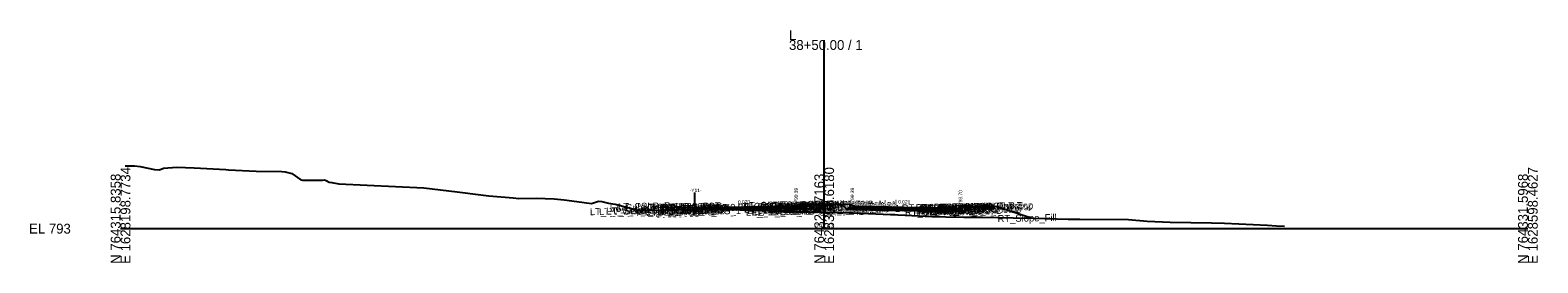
# Model space of a CAD drawing. Extents: x -26 to 4403, y -510 to 9556.
# Drawn here: x 1974.3 to 2402.8, y 8490.3 to 8556.3 of the extents above; entities that cross this region are included whole.
import ezdxf

# ---------------------------------------------------------------- set-up
doc = ezdxf.new("R2010")
doc.units = 0
for name, color, linetype in [('Default', 7, 'Continuous'), ('Exist CMT Pavement', 7, 'Continuous'), ('Exist Cross Section Cell', 7, 'Continuous'), ('Exist XS Center Line Elevation Label', 7, 'Continuous'), ('Exist XS Ground Line', 7, 'Continuous'), ('Prop CMT Conc Surface', 7, 'Continuous'), ('Prop CMT Concrete Structures', 7, 'Continuous'), ('Prop CMT Pvmt Course 1', 7, 'Continuous'), ('Prop CMT Pvmt Course 1 CG', 7, 'Continuous'), ('Prop CMT Pvmt Course 2', 7, 'Continuous'), ('Prop CMT Pvmt Course 2 Wedge', 7, 'Continuous'), ('Prop CMT Pvmt Course 3', 7, 'Continuous'), ('Prop CMT Pvmt Course 3 Wedge', 7, 'Continuous'), ('Prop CMT Pvmt Surface', 7, 'Continuous'), ('Prop CMT Shear Line', 7, 'Continuous'), ('Prop CMT Slope Grass', 7, 'Continuous'), ('Prop CMT Subgrade Earthwork', 7, 'Continuous'), ('Prop XS Hydro Elevations', 7, 'Continuous'), ('Prop XS SE Text', 7, 'Continuous'), ('Prop XS Side Slope Text', 7, 'Continuous'), ('Scratch_Level_0', 7, 'Continuous')]:
    doc.layers.add(name, color=color, linetype=linetype)

msp = doc.modelspace()

# ---------------------------------------------------------------- linework, layer by layer
at = {"layer": 'Exist CMT Pavement'}
msp.add_lwpolyline([(2163.25, 8505.47), (2164.49, 8505.46), (2172.09, 8505.45), (2179.81, 8505.29), (2182.05, 8505.24), (2184.11, 8505.16), (2191.16, 8504.91)], dxfattribs=at)
at = {"layer": 'Exist Cross Section Cell'}
for p, q in [((2200, 8500), (2200, 8553.53)), ((2000, 8500), (2200, 8500)), ((2200, 8500), (2400, 8500))]:
    msp.add_line(p, q, dxfattribs=at)
at = {"layer": 'Exist XS Ground Line'}
msp.add_lwpolyline([(2001.33, 8517.83), (2003.92, 8517.84), (2005.57, 8517.68), (2009.64, 8516.83), (2011.1, 8516.7), (2012.25, 8517.13), (2015.99, 8517.44), (2020.92, 8517.24), (2029.9, 8516.75), (2030.69, 8516.73), (2038.52, 8516.36), (2045.82, 8516.21), (2046.75, 8516.1), (2048.71, 8515.64), (2051.26, 8513.85), (2051.74, 8513.81), (2052.37, 8513.81), (2054.68, 8513.79), (2057.44, 8513.77), (2058.01, 8513.83), (2058.47, 8513.7), (2059.34, 8513.22), (2060.03, 8513.07), (2062, 8512.77), (2086.24, 8511.62), (2095.72, 8510.45), (2102.42, 8509.62), (2104.66, 8509.31), (2111.64, 8508.76), (2113.24, 8508.6), (2118.29, 8508.61), (2120.7, 8508.54), (2123.29, 8508.47), (2126.13, 8508.21), (2129.69, 8507.71), (2133.88, 8507.18), (2135.88, 8507.77), (2136.76, 8507.75), (2138.69, 8507.2), (2140.55, 8506.91), (2147.02, 8505.21), (2148.45, 8505.11), (2149.98, 8505.11), (2162.31, 8505.47), (2164.49, 8505.46), (2172.09, 8505.45), (2179.81, 8505.29), (2182.05, 8505.24), (2184.11, 8505.16), (2191.16, 8504.91), (2191.68, 8504.84), (2192.06, 8504.79), (2195.56, 8504.77), (2200, 8504.67), (2207.1, 8504.51), (2207.84, 8504.52), (2208.25, 8504.46), (2214.7, 8504.2), (2222.98, 8503.83), (2230.63, 8503.47), (2232.19, 8503.45), (2234.59, 8503.37), (2239.67, 8503.28), (2244.98, 8503.25), (2258.07, 8503.02), (2258.61, 8503.05), (2259.39, 8503), (2269.35, 8502.73), (2272.69, 8502.65), (2286.48, 8502.6), (2291.82, 8502.08), (2298.32, 8501.88), (2310.04, 8501.66), (2313.82, 8501.58), (2326.04, 8501.02), (2328.54, 8500.83), (2330.86, 8500.75)], dxfattribs=at)
at = {"layer": 'Prop CMT Conc Surface'}
for points in [[(2191.25, 8506.38), (2192, 8506.39), (2192, 8506.56), (2192.76, 8506.81)], [(2208.75, 8506.38), (2208, 8506.39), (2208, 8506.56), (2207.24, 8506.81)], [(2243.25, 8506.29), (2248.25, 8506.39)], [(2236.75, 8505.82), (2238.75, 8505.7)], [(2238.75, 8505.7), (2238.75, 8506.2), (2239.25, 8506.2)]]:
    msp.add_lwpolyline(points, dxfattribs=at)
at = {"layer": 'Prop CMT Concrete Structures'}
for points in [[(2191.25, 8506.38), (2192, 8506.39), (2192, 8506.56), (2192.76, 8506.81)], [(2191.25, 8505.79), (2191.25, 8506.38)], [(2192.76, 8506.81), (2192.76, 8505.82)], [(2208.75, 8506.38), (2208, 8506.39), (2208, 8506.56), (2207.24, 8506.81)], [(2207.24, 8506.81), (2207.24, 8505.82)], [(2208.75, 8505.79), (2208.75, 8506.38)], [(2248.25, 8506.39), (2243.25, 8506.29)], [(2248.25, 8506.05), (2248.25, 8506.39)], [(2163.25, 8505.23), (2163.25, 8505.82)], [(2192.76, 8505.82), (2191.25, 8505.79)], [(2207.24, 8505.82), (2208.75, 8505.79)], [(2236.75, 8505.82), (2238.75, 8505.7), (2238.75, 8506.2), (2239.25, 8506.2)], [(2239.25, 8506.2), (2239.25, 8505.18), (2236.75, 8505.23)], [(2236.75, 8505.23), (2236.75, 8505.82)], [(2243.25, 8506.29), (2243.25, 8505.95)], [(2243.25, 8505.95), (2248.25, 8506.05)]]:
    msp.add_lwpolyline(points, dxfattribs=at)
at = {"layer": 'Prop CMT Pvmt Course 1'}
for points in [[(2191.25, 8506.38), (2163.25, 8505.82)], [(2191.25, 8506.13), (2191.25, 8506.38)], [(2208.75, 8506.38), (2236.75, 8505.82)], [(2208.75, 8506.13), (2208.75, 8506.38)], [(2163.25, 8505.57), (2191.16, 8506.13), (2191.25, 8506.13)], [(2163.25, 8505.82), (2163.25, 8505.57), (2163.25, 8505.57)], [(2236.75, 8505.57), (2208.75, 8506.13)], [(2208.75, 8506.13), (2208.75, 8506.13), (2208.75, 8506.13)], [(2236.75, 8505.82), (2236.75, 8505.57)]]:
    msp.add_lwpolyline(points, dxfattribs=at)
at = {"layer": 'Prop CMT Pvmt Course 1 CG'}
for points in [[(2163.25, 8504.9), (2163.25, 8505.23)], [(2191.25, 8505.79), (2193.26, 8505.83), (2193.59, 8505.51)], [(2191.25, 8505.46), (2191.25, 8505.79)], [(2193.59, 8505.51), (2191.25, 8505.46)], [(2208.75, 8505.79), (2206.74, 8505.83), (2206.41, 8505.51)], [(2206.41, 8505.51), (2208.75, 8505.46)], [(2208.75, 8505.46), (2208.75, 8505.79)], [(2236.75, 8505.23), (2239.75, 8505.17), (2240.09, 8504.83)], [(2236.75, 8504.9), (2236.75, 8505.23)], [(2240.09, 8504.83), (2236.75, 8504.9)]]:
    msp.add_lwpolyline(points, dxfattribs=at)
at = {"layer": 'Prop CMT Pvmt Course 2'}
for points in [[(2163.25, 8505.23), (2163.25, 8505.23), (2163.25, 8505.57), (2163.25, 8505.57)], [(2163.25, 8505.57), (2163.25, 8505.23)], [(2191.16, 8506.13), (2191.16, 8505.79)], [(2191.25, 8506.13), (2191.16, 8506.13)], [(2191.16, 8505.79), (2191.25, 8505.79)], [(2191.25, 8505.79), (2191.25, 8506.13)], [(2208.75, 8505.79), (2208.75, 8506.13)], [(2208.75, 8506.13), (2236.75, 8505.57)], [(2236.75, 8505.23), (2208.75, 8505.79)], [(2236.75, 8505.57), (2236.75, 8505.23)]]:
    msp.add_lwpolyline(points, dxfattribs=at)
at = {"layer": 'Prop CMT Pvmt Course 2 Wedge'}
for points in [[(2163.25, 8505.57), (2164.49, 8505.59), (2172.09, 8505.74), (2179.81, 8505.9), (2182.05, 8505.94), (2184.11, 8505.98), (2191.16, 8506.13), (2191.16, 8506.13)], [(2191.16, 8505.79), (2191.16, 8505.79), (2184.11, 8505.65), (2182.05, 8505.61), (2179.81, 8505.57), (2173.06, 8505.43), (2172.09, 8505.45), (2164.49, 8505.46), (2163.25, 8505.47)], [(2163.25, 8505.47), (2163.25, 8505.57)], [(2191.16, 8506.13), (2191.16, 8505.79)]]:
    msp.add_lwpolyline(points, dxfattribs=at)
at = {"layer": 'Prop CMT Pvmt Course 3'}
for points in [[(2163.25, 8505.23), (2163.25, 8505.23), (2163.25, 8504.9), (2163.25, 8504.9)], [(2163.25, 8504.9), (2163.25, 8505.23)], [(2191.25, 8505.79), (2191.16, 8505.79)], [(2191.16, 8505.79), (2191.16, 8505.46)], [(2191.16, 8505.46), (2191.25, 8505.46)], [(2191.25, 8505.46), (2191.25, 8505.79)], [(2208.75, 8505.79), (2236.75, 8505.23)], [(2208.75, 8505.46), (2208.75, 8505.79)], [(2236.75, 8504.9), (2208.75, 8505.46)], [(2236.75, 8505.23), (2236.75, 8504.9)]]:
    msp.add_lwpolyline(points, dxfattribs=at)
at = {"layer": 'Prop CMT Pvmt Course 3 Wedge'}
for points in [[(2173.07, 8505.43), (2179.81, 8505.57)], [(2191.16, 8504.91), (2191.16, 8504.91), (2184.11, 8505.16), (2182.05, 8505.24), (2179.81, 8505.29), (2173.07, 8505.43)], [(2179.81, 8505.57), (2182.05, 8505.61), (2184.11, 8505.65), (2191.16, 8505.79), (2191.16, 8505.79)], [(2191.16, 8505.79), (2191.16, 8504.91)]]:
    msp.add_lwpolyline(points, dxfattribs=at)
at = {"layer": 'Prop CMT Pvmt Surface'}
for points in [[(2191.25, 8506.38), (2163.25, 8505.82)], [(2208.75, 8506.38), (2236.75, 8505.82)]]:
    msp.add_lwpolyline(points, dxfattribs=at)
at = {"layer": 'Prop CMT Shear Line'}
msp.add_line((2163.25, 8504.01), (2163.25, 8510.28), dxfattribs=at)
at = {"layer": 'Prop CMT Slope Grass'}
for points in [[(2192.76, 8506.81), (2200, 8506.95)], [(2207.24, 8506.81), (2200, 8506.95)], [(2239.25, 8506.2), (2248.75, 8506.39), (2258.81, 8503.03)]]:
    msp.add_lwpolyline(points, dxfattribs=at)
at = {"layer": 'Prop CMT Subgrade Earthwork'}
for points in [[(2194.93, 8506.85), (2193.59, 8505.51)], [(2205.07, 8506.85), (2206.41, 8505.51)], [(2163.25, 8504.9), (2163.25, 8505.23)], [(2163.25, 8504.9), (2163.25, 8504.9)], [(2163.25, 8504.9), (2163.25, 8504.9)], [(2191.25, 8505.46), (2191.16, 8505.46)], [(2191.16, 8505.46), (2191.16, 8504.91)], [(2193.59, 8505.51), (2191.25, 8505.46)], [(2191.25, 8505.46), (2191.25, 8505.46)], [(2206.41, 8505.51), (2208.75, 8505.46)], [(2208.75, 8505.46), (2236.75, 8504.9)], [(2208.75, 8505.46), (2208.75, 8505.46)], [(2208.75, 8505.46), (2208.75, 8505.46)], [(2236.75, 8504.9), (2240.09, 8504.83), (2241.5, 8506.24)], [(2236.75, 8504.9), (2236.75, 8504.9)]]:
    msp.add_lwpolyline(points, dxfattribs=at)

# ---------------------------------------------------------------- texts
at = {"layer": 'Default'}
msp.add_text('-', height=0.0001, dxfattribs=at).set_placement((2000, 8500))
at = {"layer": 'Exist Cross Section Cell'}
for s, p in [('38+50.00 / 1', (2190, 8550.73)), ('L', (2190, 8553.53)), ('EL 793', (1974, 8498.6))]:
    msp.add_text(s, height=2.8, dxfattribs=at).set_placement(p)
for s, p in [('N 764315.8358', (2000, 8490)), ('E 1628198.7734', (2002.8, 8490)), ('N 764323.7163', (2200, 8490)), ('E 1628398.6180', (2202.8, 8490)), ('N 764331.5968', (2400, 8490)), ('E 1628598.4627', (2402.8, 8490))]:
    msp.add_text(s, height=2.8, rotation=90, dxfattribs=at).set_placement(p)
at = {"layer": 'Exist XS Center Line Elevation Label'}
msp.add_text('797.67', height=1.2, dxfattribs=at).set_placement((2197.59, 8500.07))
at = {"layer": 'Prop XS Hydro Elevations'}
for s, rotation, p in [('-Y11-', 360, (2161.77, 8510.37)), ('799.39', 90, (2192.5, 8507.39)), ('799.39', 90, (2208.5, 8507.39)), ('798.70', 90, (2239.25, 8506.7))]:
    msp.add_text(s, height=1, rotation=rotation, dxfattribs=at).set_placement(p)
at = {"layer": 'Prop XS SE Text'}
for rotation, p in [(1.1458, (2175.48, 8507.06)), (358.8543, (2221.02, 8507.13))]:
    msp.add_text('0.020', height=1, rotation=rotation, dxfattribs=at).set_placement(p)
at = {"layer": 'Prop XS Side Slope Text'}
msp.add_text('3:1', height=1, rotation=341.5647, dxfattribs=at).set_placement((2253.26, 8505.67))
at = {"layer": 'Scratch_Level_0'}
for s, p in [('LT_Slope_Fill', (2138.13, 8503.98)), ('LT_Sub_Trench_Out_DLT', (2139.09, 8504.85)), ('LT_CSLP_Pnt', (2141.44, 8505.19)), ('LT_CG_Top_Face', (2148.53, 8504.94)), ('LT_CG_Top_BOC', (2149.06, 8504.96)), ('LT_CG_Bot_BOC', (2149.09, 8503.95)), ('LT_CG_Top_Gut', (2149.51, 8504.46)), ('38+50.00', (2152.66, 8505.09)), ('LT_PV2_OEEOP', (2152.58, 8504.35)), ('LT_PV3_OEEOP', (2152.58, 8504.02)), ('LT_CG_Bot_IE', (2153.19, 8504.03)), ('LT_PV2_OEOT', (2153.45, 8504.37)), ('LT_PV3_OEOT', (2153.45, 8504.04)), ('LT_PV1_OEOT', (2154.01, 8504.63)), ('38+50.00', (2154.21, 8505.06)), ('38+50.00', (2167.28, 8504.9)), ('LT_CG_Top_Face_Med', (2175.39, 8505.23)), ('LT_CG_Top_Gut_Med', (2176.37, 8505.08)), ('LT_CG_Top_BOC_Med', (2177.18, 8505.5)), ('LT_CG_Bot_BOC_Med', (2177.21, 8504.51)), ('LT_CG_Bot_IE_Med', (2177.34, 8504.52)), ('LT_Sub_IEOT_CG_1', (2178.14, 8504.2)), ('LT_Sub_IEEOP', (2181.04, 8504.26)), ('LT_PV2_IEEOP', (2181.14, 8504.93)), ('LT_PV3_IEEOP', (2181.14, 8504.59)), ('LT_CG1_Shelf_In', (2181.46, 8504.6)), ('LT_Sub_PGL', (2182.39, 8504.28)), ('LT_PV2_PGL', (2182.48, 8504.95)), ('LT_PV3_PGL', (2182.48, 8504.62)), ('LT_PV1_PGL', (2183.05, 8505.21)), ('LT_Sub_DLT_In', (2183.9, 8505.63)), ('LT_Sub_IEOP', (2184.36, 8504.32)), ('38+50.00', (2185.15, 8505.26)), ('38+50.00', (2186.29, 8505.68)), ('MD_Crown Point', (2187.09, 8505.7)), ('38+50.00', (2190.97, 8505.77)), ('RT_CG_Top_Face_Med', (2191.35, 8505.23)), ('RT_CG_Top_BOC_Med', (2191.61, 8505.5)), ('RT_CG_Bot_BOC_Med', (2191.64, 8504.51)), ('RT_CG_Top_Gut_Med', (2192.32, 8505.08)), ('RT_Sub_DLT_In', (2193.99, 8505.63)), ('RT_CG_Bot_IE_Med', (2194.79, 8504.51)), ('RT_CG1_Shelf_In', (2194.89, 8504.6)), ('RT_Sub_IEOT_CG_1', (2195.59, 8504.2)), ('RT_Sub_IEOP', (2197.14, 8504.32)), ('RT_Sub_OEEOP', (2197.94, 8504.24)), ('RT_PV2_OEEOP', (2198.03, 8504.91)), ('RT_PV3_OEEOP', (2198.03, 8504.58)), ('38+50.00', (2198.34, 8505.72)), ('RT_Sub_IEEOP', (2198.58, 8504.26)), ('RT_PV2_IEEOP', (2198.68, 8504.93)), ('RT_Sub_PGL', (2199.84, 8504.28)), ('RT_PV2_PGL', (2199.94, 8504.95)), ('RT_PV1_PGL', (2200.5, 8505.21)), ('38+50.00', (2200.85, 8505.56)), ('38+50.00', (2201.27, 8505.34)), ('38+50.00', (2201.91, 8505.25)), ('RT_Sub_Trench_Out_DLT', (2222.04, 8504.85)), ('RT_CG_Top_Face', (2225.99, 8504.94)), ('RT_CG_Bot_IE', (2226.64, 8504.03)), ('RT_PV2_OEOT', (2226.9, 8504.37)), ('RT_PV3_OEOT', (2226.9, 8504.04)), ('RT_CG_Top_Gut', (2226.96, 8504.46)), ('RT_PV1_OEOT', (2227.47, 8504.63)), ('RT_CG_Top_BOC', (2227.51, 8504.96)), ('RT_CG_Bot_BOC', (2227.54, 8503.95)), ('RT_SDWK_In_Top', (2231.08, 8505.04)), ('RT_SDWK_In_Bot', (2231.11, 8504.71)), ('38+50.00', (2232.38, 8505.06)), ('38+50.00', (2232.84, 8505.07)), ('RT_SDWK_Out_Top', (2234.46, 8505.11)), ('RT_SDWK_Out_Bot', (2234.49, 8504.78)), ('RT_CSLP_Pnt', (2238.9, 8505.19)), ('38+50.00', (2244.86, 8504.31)), ('LT_PV_Sub_Tie_Out', (2133.42, 8503.81)), ('LT_PV_OEEOP_EG', (2136.02, 8503.86)), ('LT_CG1_Shelf_Out', (2146.82, 8503.91)), ('LT_Sub_OEOT_CG_1', (2149.49, 8503.63)), ('LT_Sub_OEOP', (2150.04, 8503.64)), ('LT_Sub_OEEOP', (2152.49, 8503.69)), ('LT_Sub_OEOT', (2153.35, 8503.7)), ('LT_PV_Sub_Tie_In', (2177.75, 8503.64)), ('LT_PV_IEEOP_EG', (2179.37, 8503.68)), ('RT_Sub_OEOT_CG_1', (2222.95, 8503.62)), ('RT_CG1_Shelf_Out', (2226.28, 8503.9)), ('RT_Sub_OEOT', (2226.8, 8503.7)), ('RT_Sub_OEOP', (2230.18, 8503.64)), ('RT_Slope_Fill', (2249.3, 8501.84))]:
    msp.add_text(s, height=2, rotation=1.1458, dxfattribs=at).set_placement(p)

doc.saveas('drawing.dxf')
